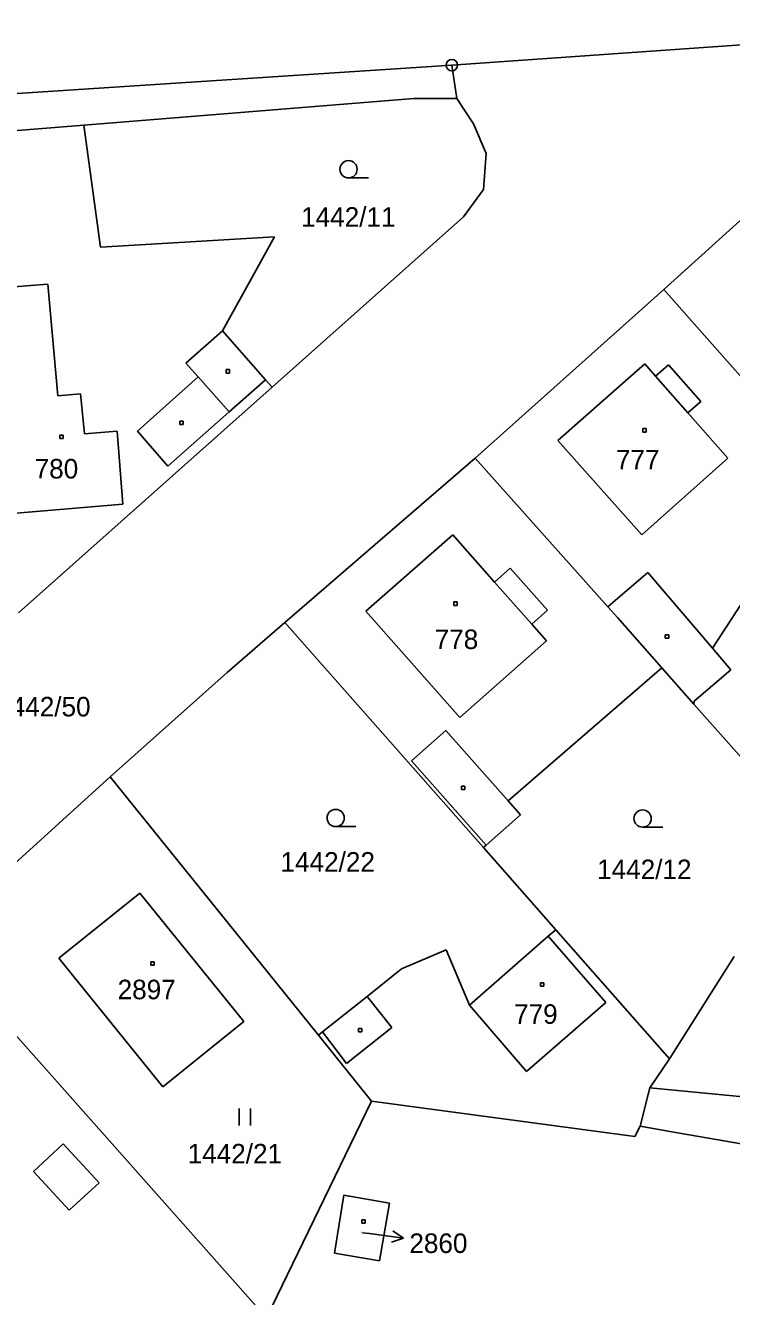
# Model space of a CAD drawing. Extents: x -795483 to -789093, y -1112258 to -1108741.
# Drawn here: x -792761.3 to -792699.9, y -1110275.1 to -1110164.5 of the extents above; entities that cross this region are included whole.
import ezdxf

# ---------------------------------------------------------------- set-up
doc = ezdxf.new("R2010")
doc.units = 0
for name, color, linetype in [('Komunikace', 7, 'Continuous'), ('Vrstva 1', 7, 'Continuous'), ('Vrstva 14', 7, 'Continuous'), ('Vrstva 15', 7, 'Continuous'), ('Vrstva 16', 7, 'Continuous'), ('Vrstva 2', 7, 'Continuous'), ('Vrstva 23', 7, 'Continuous'), ('Vrstva 25', 7, 'Continuous'), ('Vrstva 28', 7, 'Continuous')]:
    doc.layers.add(name, color=color, linetype=linetype)

msp = doc.modelspace()

# ---------------------------------------------------------------- linework, layer by layer
at = {"layer": 'Komunikace'}
msp.add_line((-792731.98, -1110269.55), (-792731.39, -1110269.62), dxfattribs=at)
at = {"layer": 'Vrstva 1'}
for p, q in [((-792724.21, -1110167.98), (-792674.54, -1110164.53)), ((-792821.65, -1110174.35), (-792724.21, -1110167.98)), ((-792724.21, -1110167.98), (-792723.77, -1110170.89)), ((-792756.24, -1110173.2), (-792727.53, -1110170.89)), ((-792727.53, -1110170.89), (-792723.77, -1110170.89)), ((-792723.77, -1110170.89), (-792722.34, -1110173.08)), ((-792765.3, -1110173.93), (-792756.24, -1110173.2)), ((-792756.24, -1110173.2), (-792754.78, -1110183.81)), ((-792722.34, -1110173.08), (-792721.22, -1110175.68)), ((-792705.77, -1110187.49), (-792689.06, -1110172.4)), ((-792721.22, -1110175.68), (-792721.47, -1110178.8)), ((-792721.47, -1110178.8), (-792723.19, -1110181.17)), ((-792723.19, -1110181.17), (-792739.85, -1110196)), ((-792754.78, -1110183.81), (-792739.65, -1110182.91)), ((-792739.65, -1110182.91), (-792744.17, -1110191.11)), ((-792722.17, -1110202.16), (-792705.77, -1110187.49)), ((-792705.77, -1110187.49), (-792691.37, -1110203.81)), ((-792744.17, -1110191.11), (-792740.43, -1110195.35)), ((-792740.43, -1110195.35), (-792739.85, -1110196)), ((-792739.85, -1110196), (-792761.9, -1110215.62)), ((-792738.73, -1110216.47), (-792722.17, -1110202.16)), ((-792722.17, -1110202.16), (-792710.64, -1110215.1)), ((-792694.44, -1110207.78), (-792701.55, -1110218.71)), ((-792709.81, -1110216.03), (-792710.64, -1110215.1)), ((-792743.75, -1110220.82), (-792738.73, -1110216.47)), ((-792738.73, -1110216.47), (-792721.47, -1110236.05)), ((-792709.81, -1110216.03), (-792705.94, -1110220.41)), ((-792701.55, -1110218.71), (-792699.94, -1110220.59)), ((-792753.93, -1110229.88), (-792743.75, -1110220.82)), ((-792705.94, -1110220.41), (-792719.31, -1110231.99)), ((-792705.94, -1110220.41), (-792703.16, -1110223.56)), ((-792699.94, -1110220.59), (-792703.14, -1110223.32)), ((-792703.14, -1110223.32), (-792703.16, -1110223.56)), ((-792703.16, -1110223.56), (-792693.01, -1110235.03)), ((-792769.54, -1110244.05), (-792753.93, -1110229.88)), ((-792753.93, -1110229.88), (-792735.82, -1110252.35)), ((-792719.31, -1110231.99), (-792718.24, -1110233.2)), ((-792718.24, -1110233.2), (-792721.24, -1110235.85)), ((-792721.24, -1110235.85), (-792721.47, -1110236.05)), ((-792721.47, -1110236.05), (-792715.17, -1110243.19)), ((-792758.41, -1110245.67), (-792751.37, -1110240.02)), ((-792751.37, -1110240.02), (-792742.31, -1110251.18)), ((-792769.54, -1110244.05), (-792740.34, -1110276.96)), ((-792722.68, -1110249.74), (-792715.82, -1110243.76)), ((-792715.82, -1110243.76), (-792715.17, -1110243.19)), ((-792715.17, -1110243.19), (-792705.28, -1110254.41)), ((-792728.6, -1110246.6), (-792724.72, -1110244.95)), ((-792724.72, -1110244.95), (-792722.68, -1110249.74)), ((-792749.36, -1110256.86), (-792758.41, -1110245.67)), ((-792699.65, -1110245.51), (-792705.28, -1110254.41)), ((-792731.57, -1110248.99), (-792728.6, -1110246.6)), ((-792735.46, -1110252.06), (-792731.57, -1110248.99)), ((-792742.31, -1110251.18), (-792749.36, -1110256.86)), ((-792735.82, -1110252.35), (-792735.46, -1110252.06)), ((-792735.82, -1110252.35), (-792731.19, -1110258.09)), ((-792705.28, -1110254.41), (-792707, -1110256.94)), ((-792707, -1110256.94), (-792707.82, -1110260.28)), ((-792681.54, -1110259.37), (-792707, -1110256.94)), ((-792731.19, -1110258.09), (-792740.34, -1110276.96)), ((-792731.19, -1110258.09), (-792708.3, -1110261.17)), ((-792708.3, -1110261.17), (-792707.82, -1110260.28)), ((-792707.82, -1110260.28), (-792705.08, -1110260.76)), ((-792705.08, -1110260.76), (-792682.38, -1110264.72)), ((-792734.43, -1110271.34), (-792733.61, -1110266.29)), ((-792733.61, -1110266.29), (-792729.64, -1110266.97)), ((-792729.64, -1110266.97), (-792730.5, -1110271.99)), ((-792730.5, -1110271.99), (-792734.43, -1110271.34))]:
    msp.add_line(p, q, dxfattribs=at)
at = {"layer": 'Vrstva 16'}
for p, q in [((-792728.42, -1110270.01), (-792729.34, -1110269.38)), ((-792731.39, -1110269.62), (-792728.42, -1110270.01)), ((-792728.42, -1110270.01), (-792729.47, -1110270.37))]:
    msp.add_line(p, q, dxfattribs=at)
at = {"layer": 'Vrstva 2'}
for p, q in [((-792759.37, -1110187.03), (-792763.92, -1110187.38)), ((-792758.49, -1110196.74), (-792759.37, -1110187.03)), ((-792744.17, -1110191.11), (-792747.35, -1110193.91)), ((-792747.35, -1110193.91), (-792746.28, -1110195.11)), ((-792715, -1110200.64), (-792707.43, -1110193.98)), ((-792707.43, -1110193.98), (-792706.49, -1110195.05)), ((-792706.49, -1110195.05), (-792705.36, -1110194.06)), ((-792705.36, -1110194.06), (-792702.55, -1110197.24)), ((-792746.28, -1110195.11), (-792751.56, -1110199.82)), ((-792746.28, -1110195.11), (-792743.58, -1110198.15)), ((-792740.43, -1110195.35), (-792743.58, -1110198.15)), ((-792706.49, -1110195.05), (-792703.67, -1110198.23)), ((-792756.52, -1110196.57), (-792758.49, -1110196.74)), ((-792756.17, -1110200.07), (-792756.52, -1110196.57)), ((-792702.55, -1110197.24), (-792703.67, -1110198.23)), ((-792748.91, -1110202.88), (-792743.58, -1110198.15)), ((-792703.67, -1110198.23), (-792700.21, -1110202.16)), ((-792753.33, -1110199.81), (-792756.17, -1110200.07)), ((-792752.83, -1110206.18), (-792753.33, -1110199.81)), ((-792751.56, -1110199.82), (-792748.91, -1110202.88)), ((-792707.69, -1110208.84), (-792715, -1110200.64)), ((-792700.21, -1110202.16), (-792707.69, -1110208.84)), ((-792762.43, -1110206.98), (-792752.83, -1110206.18)), ((-792731.7, -1110215.49), (-792724.14, -1110208.83)), ((-792724.14, -1110208.83), (-792720.5, -1110212.95)), ((-792720.5, -1110212.95), (-792719.13, -1110211.73)), ((-792719.13, -1110211.73), (-792715.88, -1110215.4)), ((-792720.5, -1110212.95), (-792717.26, -1110216.62)), ((-792710.4, -1110214.9), (-792707.17, -1110212.13)), ((-792707.17, -1110212.13), (-792701.55, -1110218.71)), ((-792715.88, -1110215.4), (-792717.26, -1110216.62)), ((-792710.4, -1110214.9), (-792710.64, -1110215.1)), ((-792723.52, -1110224.72), (-792731.7, -1110215.49)), ((-792717.26, -1110216.62), (-792715.99, -1110218.05)), ((-792715.99, -1110218.05), (-792723.52, -1110224.72)), ((-792727.73, -1110228.5), (-792724.75, -1110225.87)), ((-792724.75, -1110225.87), (-792719.31, -1110231.99)), ((-792727.73, -1110228.5), (-792721.24, -1110235.85)), ((-792710.81, -1110249.52), (-792715.82, -1110243.76)), ((-792731.57, -1110248.99), (-792729.43, -1110251.71)), ((-792717.72, -1110255.53), (-792710.81, -1110249.52)), ((-792722.68, -1110249.74), (-792717.72, -1110255.53)), ((-792729.43, -1110251.71), (-792733.38, -1110254.82)), ((-792733.38, -1110254.82), (-792735.46, -1110252.06)), ((-792760.62, -1110264.22), (-792758.03, -1110261.82)), ((-792758.03, -1110261.82), (-792754.91, -1110265.2)), ((-792757.5, -1110267.59), (-792760.62, -1110264.22)), ((-792754.91, -1110265.2), (-792757.5, -1110267.59))]:
    msp.add_line(p, q, dxfattribs=at)
at = {"layer": 'Vrstva 23'}
for p, q in [((-792733.2, -1110177.79), (-792731.45, -1110177.79)), ((-792734.32, -1110234.22), (-792732.57, -1110234.22)), ((-792707.62, -1110234.27), (-792705.87, -1110234.27)), ((-792742.73, -1110260.23), (-792742.73, -1110258.73)), ((-792741.73, -1110258.73), (-792741.73, -1110260.23))]:
    msp.add_line(p, q, dxfattribs=at)
for centre in [(-792733.2, -1110177.04), (-792734.32, -1110233.47), (-792707.62, -1110233.52)]:
    msp.add_circle(centre, 0.75, dxfattribs=at)
at = {"layer": 'Vrstva 25'}
for p, q in [((-792743.86, -1110194.47), (-792743.56, -1110194.47)), ((-792743.86, -1110194.77), (-792743.86, -1110194.47)), ((-792743.56, -1110194.77), (-792743.86, -1110194.77)), ((-792743.56, -1110194.47), (-792743.56, -1110194.77)), ((-792747.89, -1110198.94), (-792747.59, -1110198.94)), ((-792747.89, -1110199.24), (-792747.89, -1110198.94)), ((-792747.59, -1110199.24), (-792747.89, -1110199.24)), ((-792747.59, -1110198.94), (-792747.59, -1110199.24)), ((-792707.61, -1110199.6), (-792707.31, -1110199.6)), ((-792707.61, -1110199.9), (-792707.61, -1110199.6)), ((-792707.31, -1110199.9), (-792707.61, -1110199.9)), ((-792707.31, -1110199.6), (-792707.31, -1110199.9)), ((-792758.32, -1110200.17), (-792758.02, -1110200.17)), ((-792758.32, -1110200.47), (-792758.32, -1110200.17)), ((-792758.02, -1110200.47), (-792758.32, -1110200.47)), ((-792758.02, -1110200.17), (-792758.02, -1110200.47)), ((-792724.04, -1110214.68), (-792723.74, -1110214.68)), ((-792724.04, -1110214.98), (-792724.04, -1110214.68)), ((-792723.74, -1110214.98), (-792724.04, -1110214.98)), ((-792723.74, -1110214.68), (-792723.74, -1110214.98)), ((-792705.64, -1110217.54), (-792705.34, -1110217.54)), ((-792705.64, -1110217.84), (-792705.64, -1110217.54)), ((-792705.34, -1110217.54), (-792705.34, -1110217.84)), ((-792705.34, -1110217.84), (-792705.64, -1110217.84)), ((-792723.38, -1110230.69), (-792723.08, -1110230.69)), ((-792723.38, -1110230.99), (-792723.38, -1110230.69)), ((-792723.08, -1110230.69), (-792723.08, -1110230.99)), ((-792723.08, -1110230.99), (-792723.38, -1110230.99)), ((-792750.4, -1110245.97), (-792750.1, -1110245.97)), ((-792750.4, -1110246.27), (-792750.4, -1110245.97)), ((-792750.1, -1110246.27), (-792750.4, -1110246.27)), ((-792750.1, -1110245.97), (-792750.1, -1110246.27)), ((-792716.51, -1110247.8), (-792716.21, -1110247.8)), ((-792716.51, -1110248.1), (-792716.51, -1110247.8)), ((-792716.21, -1110248.1), (-792716.51, -1110248.1)), ((-792716.21, -1110247.8), (-792716.21, -1110248.1)), ((-792732.33, -1110251.78), (-792732.03, -1110251.78)), ((-792732.33, -1110252.08), (-792732.33, -1110251.78)), ((-792732.03, -1110251.78), (-792732.03, -1110252.08)), ((-792732.03, -1110252.08), (-792732.33, -1110252.08)), ((-792732.05, -1110268.42), (-792731.75, -1110268.42)), ((-792732.05, -1110268.72), (-792732.05, -1110268.42)), ((-792731.75, -1110268.42), (-792731.75, -1110268.72)), ((-792731.75, -1110268.72), (-792732.05, -1110268.72))]:
    msp.add_line(p, q, dxfattribs=at)
at = {"layer": 'Vrstva 28'}
for radius in [0.5, 0.01]:
    msp.add_circle((-792724.21, -1110167.98), radius, dxfattribs=at)

# ---------------------------------------------------------------- texts
at = {"layer": 'Vrstva 14'}
for s, p in [('1442/11', (-792737.33, -1110182.04)), ('1442/50', (-792763.86, -1110224.64)), ('1442/22', (-792739.12, -1110238.14)), ('1442/12', (-792711.58, -1110238.79)), ('1442/21', (-792747.2, -1110263.52))]:
    msp.add_text(s, height=1.7, dxfattribs=at).set_placement(p)
at = {"layer": 'Vrstva 15'}
for s, height, p in [('777', 1.7, (-792709.94, -1110203.15)), ('780', 1.7, (-792760.51, -1110203.94)), ('778', 1.7, (-792725.71, -1110218.78)), ('2897', 1.7, (-792753.29, -1110249.24)), ('779', 1.7, (-792718.8, -1110251.38)), ('2860', 0.1, (-792732.15, -1110269.55))]:
    msp.add_text(s, height=height, dxfattribs=at).set_placement(p)
at = {"layer": 'Vrstva 16'}
msp.add_text('2860', height=1.7, dxfattribs=at).set_placement((-792727.91, -1110271.31))

doc.saveas('drawing.dxf')
